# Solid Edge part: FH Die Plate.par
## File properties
Author: Dan
Template: metric part.par
Last saved by: Dan
Revision: 59
Application: Solid Edge
Material: Steel
Face Style: Steel
Fill Style: ANSI32(Steel)
Virtual Style: Machined steel
Coef. of Thermal Exp: 1.3e-05
Thermal Conductivity: 32.0
Specific Heat: 481.0
Modulus of Elasticity: 199947953000.0
Poisson's Ratio: 0.29
Yield Stress: 262000766.0
Ultimate Stress: 358527364.0
Elongation: 0.0
Density: 7833.000 kg/m^3
Accuracy: 0.990
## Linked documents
Wheel.asm
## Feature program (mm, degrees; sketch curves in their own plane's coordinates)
sketch for "unnamed Protrusion 1" plane through (0, 0, 0) normal (0, 0, 1) x-axis (1, 0, 0)
  hole centre (-125, 0) bore radius 5.053
extrude "unnamed Protrusion 1" add finite 36 along -normal
sketch for "Hole_1" plane through (0, 0, -36) normal (0, 0, -1) x-axis (-1, 0, 0)
hole "Hole_1" diameter 116 through  VBottomAngle = 118 deg
sketch for "unnamed Hole 1" plane through (0, 0, -36) normal (0, 0, -1) x-axis (-1, 0, 0)
hole "unnamed Hole 1" through
sketch for "unnamed Hole 2" plane through (0, 0, -36) normal (0, 0, -1) x-axis (-1, 0, 0)
  hole centre (75, 75) bore radius 58
hole "unnamed Hole 2" through
sketch for "unnamed Hole 3" plane through (0, 0, -36) normal (0, 0, -1) x-axis (-1, 0, 0)
  hole centre (75, -75) bore radius 58
hole "unnamed Hole 3" through
pattern "unnamed Pattern 3" of "Hole_1", "unnamed Hole 1", "unnamed Hole 2", "unnamed Hole 3"
sketch for "Hole_9" plane through (0, 0, -36) normal (0, 0, -1) x-axis (1, 0, 0)
hole "Hole_9" diameter 42 through  CounterBoreDepth = 6 mm; VBottomAngle = 118 deg
sketch for "unnamed Hole 4" plane through (0, 0, -36) normal (0, 0, -1) x-axis (1, 0, 0)
hole "unnamed Hole 4" through
sketch for "unnamed Hole 5" plane through (0, 0, -36) normal (0, 0, -1) x-axis (1, 0, 0)
  hole centre (170, -170) bore radius 21
hole "unnamed Hole 5" through
sketch for "unnamed Hole 6" plane through (0, 0, -36) normal (0, 0, -1) x-axis (1, 0, 0)
  hole centre (-170, -170) bore radius 21
hole "unnamed Hole 6" through
pattern "unnamed Pattern 1" of "Hole_9", "unnamed Hole 4", "unnamed Hole 5", "unnamed Hole 6"
sketch for "Hole_13" plane through (0, 0, -36) normal (0, 0, -1) x-axis (1, 0, 0)
  hole centre (-170, 106) bore radius 6
hole "Hole_13" diameter 12 through  VBottomAngle = 118 deg
sketch for "unnamed Hole 7" plane through (0, 0, -36) normal (0, 0, -1) x-axis (1, 0, 0)
  hole centre (170, 106) bore radius 6
hole "unnamed Hole 7" through
sketch for "unnamed Hole 8" plane through (0, 0, -36) normal (0, 0, -1) x-axis (1, 0, 0)
  hole centre (-170, -106) bore radius 6
hole "unnamed Hole 8" through
sketch for "unnamed Hole 9" plane through (0, 0, -36) normal (0, 0, -1) x-axis (1, 0, 0)
hole "unnamed Hole 9" through
pattern "unnamed Pattern 2" of "Hole_13", "unnamed Hole 7", "unnamed Hole 8", "unnamed Hole 9"
boolean "unnamed Boolean 1"
sketch for "Hole_17" plane through (0, 0, 0) normal (1, 0, 0) x-axis (0, 1, 0)
hole "Hole_17" diameter 6 through  VBottomAngle = 118 deg
sketch for "unnamed Hole 10" plane through (0, 0, 0) normal (1, 0, 0) x-axis (0, 1, 0)
  hole centre (-62.5, -27) bore radius 3
hole "unnamed Hole 10" through
sketch for "unnamed Hole 11" plane through (0, 0, 0) normal (1, 0, 0) x-axis (0, 1, 0)
  hole centre (62.5, -27) bore radius 3
hole "unnamed Hole 11" through
sketch for "unnamed Hole 12" plane through (0, 0, 0) normal (1, 0, 0) x-axis (0, 1, 0)
  hole centre (87.5, -27) bore radius 3
hole "unnamed Hole 12" through
pattern "unnamed Pattern 4" of "Hole_17", "unnamed Hole 10", "unnamed Hole 11", "unnamed Hole 12"
sketch for "Hole_21" plane through (-198, 0, -18) normal (-1, 0, 0) x-axis (0, 1, 0)
  hole centre (120, -180) bore radius 5.25
hole "Hole_21" nominal diameter 12 finite  VBottomAngle = 118 deg
sketch for "unnamed Hole 13" plane through (-198, 0, -18) normal (-1, 0, 0) x-axis (0, 1, 0)
hole "unnamed Hole 13" finite
pattern "unnamed Pattern 5" of "Hole_21", "unnamed Hole 13"
sketch for "Hole_24" plane through (198, 0, -18) normal (1, 0, 0) x-axis (0, -1, 0)
  hole centre (-125, 0) bore radius 5.053
  dimension (linear) = 125
hole "Hole_24" finite
sketch for "unnamed Hole 14" plane through (198, 0, -18) normal (1, 0, 0) x-axis (0, -1, 0)
  hole centre (125, 0) bore radius 5.053
hole "unnamed Hole 14" finite
pattern "unnamed Pattern 6" of "Hole_24", "unnamed Hole 14"
delete faces "unnamed DeleteFaces 1"
sketch for "Hole_26" plane through (0, 0, 0) normal (0, 0, 1) x-axis (-1, 0, 0)
hole "Hole_26" diameter 20 finite
sketch for "unnamed Hole 15" plane through (0, 0, 0) normal (0, 0, 1) x-axis (-1, 0, 0)
hole "unnamed Hole 15" finite
sketch for "unnamed Hole 16" plane through (0, 0, 0) normal (0, 0, 1) x-axis (-1, 0, 0)
hole "unnamed Hole 16" finite
sketch for "unnamed Hole 17" plane through (0, 0, 0) normal (0, 0, 1) x-axis (-1, 0, 0)
  hole centre (170, -106) bore radius 10
hole "unnamed Hole 17" finite
pattern "unnamed Pattern 7" of "Hole_26", "unnamed Hole 15", "unnamed Hole 16", "unnamed Hole 17"
sketch for "Hole_30" plane through (0, 0, 0) normal (0, 0, 1) x-axis (1, 0, 0)
hole "Hole_30" diameter 10.5 through  CounterBoreDepth = 10.5 mm
sketch for "unnamed Hole 18" plane through (0, 0, 0) normal (0, 0, 1) x-axis (1, 0, 0)
hole "unnamed Hole 18" through
sketch for "unnamed Hole 19" plane through (0, 0, 0) normal (0, 0, 1) x-axis (1, 0, 0)
hole "unnamed Hole 19" through
sketch for "unnamed Hole 20" plane through (0, 0, 0) normal (0, 0, 1) x-axis (1, 0, 0)
  hole centre (25, 0) bore radius 5.25
hole "unnamed Hole 20" through
sketch for "unnamed Hole 21" plane through (0, 0, 0) normal (0, 0, 1) x-axis (1, 0, 0)
  hole centre (-25, 0) bore radius 5.25
hole "unnamed Hole 21" through
sketch for "unnamed Hole 22" plane through (0, 0, 0) normal (0, 0, 1) x-axis (1, 0, 0)
  hole centre (-120, -180) bore radius 5.25
hole "unnamed Hole 22" through
pattern "unnamed Pattern 8" of "Hole_30", "unnamed Hole 18", "unnamed Hole 19", "unnamed Hole 20", "unnamed Hole 21", "unnamed Hole 22"
Other named dimensions: "CoordinateSystem_2": Y_Rotation = 90 deg; X_Translation = 75 mm; Y_Translation = 75 mm | "CopyConstruction_1": XScale = 1.015; YScale = 1.008; ZScale = 1.008 | "Hole_23": VBottomAngle = 118 deg; Diameter = 12 mm
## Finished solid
Body 1: solid body, 229 faces, 447 edges, 255 vertices, 16 separate solids.
  Faces by surface: plane 163, cylinder 31, spline 26, cone 9
  Edges by curve: line 341, circle 68, spline 34, curve on surface 4
Body 2: solid body, 229 faces, 447 edges, 255 vertices, 16 separate solids.
  Faces by surface: plane 163, cylinder 31, spline 26, cone 9
  Edges by curve: line 341, circle 68, spline 34, curve on surface 4
Body 3: solid body, 229 faces, 447 edges, 255 vertices, 16 separate solids.
  Faces by surface: plane 163, cylinder 31, spline 26, cone 9
  Edges by curve: line 341, circle 68, spline 34, curve on surface 4
Body 4: solid body, 311 faces, 567 edges, 327 vertices, 16 separate solids, 19 internal voids.
  Faces by surface: plane 196, cylinder 67, spline 36, cone 12
  Edges by curve: line 375, spline 102, circle 80, curve on surface 10
Body 5: solid body, 80 faces, 112 edges, 8 vertices.
  Faces by surface: cylinder 44, plane 24, spline 8, cone 4
  Edges by curve: circle 92, line 12, intersection 8
Bounding box of the edges (mm; curved faces can reach further): 396.000 x 396.000 x 54.820, from (-198, -198, -36) to (198, 198, 18.8199).
Cylindrical faces by radius (mm): R3 x8, R5.04 x16, R5.053 x4, R5.25 x6, R6 x4, R7.5588 x4, R8.5 x6, R9.5745 x8, R10 x4, R10.5824 x8, R13.6059 x8, R15.6218 x8, R15.9497 x8, R17.6371 x1, R17.6373 x1, R21 x4, R21.6693 x8, R22.6773 x16, R23.5 x4, R26.7093 x8, R28.5704 x1, R31.7493 x9, R36.036 x8, R38.304 x16, R38.5862 x16, R41.076 x8, R45.864 x8, R58 x4
Conical faces (half-angle, radius in mm at the cone's reference point): 1.9862 deg R16.1609 x8, 1.9862 deg R18.8591 x8, 59 deg R5.053 x4, 70.2158 deg R10.5824 x8, 70.2158 deg R14.3315 x4, 70.2158 deg R14.3576 x4, 74.9008 deg R54.45 x1, 74.9012 deg R54.4498 x1, 89.9983 deg R30.7413 x1, 89.999 deg R17.1331 x4
Planar faces by outward normal: +x 101, +y 117, +z 96, -x 101, -y 117, -z 113, oblique 64
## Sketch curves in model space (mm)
line (97.1242, -198, 0) -> (97.1242, 198, 0)
line (-102, -198, 0) -> (-102, 198, 0)
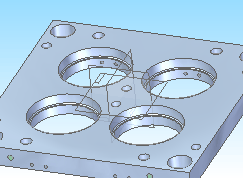
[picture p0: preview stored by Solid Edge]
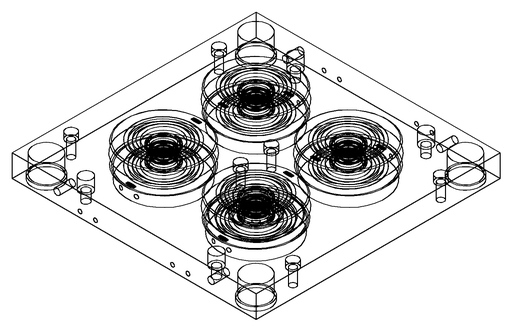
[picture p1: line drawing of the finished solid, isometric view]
